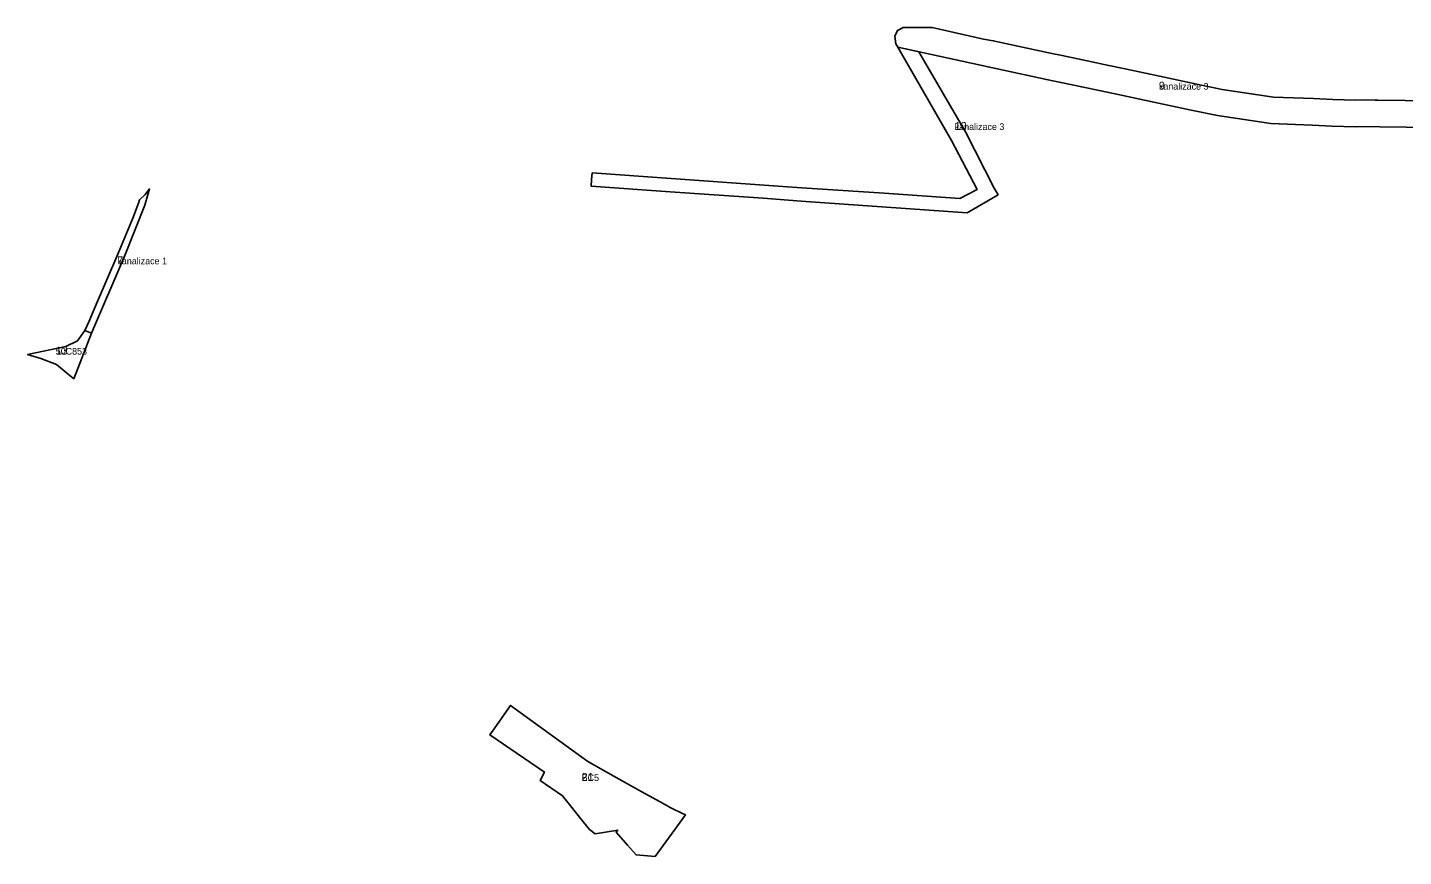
# Model space of a CAD drawing. Extents: x -540086 to -538022, y -1162553 to -1159940.
# Drawn here: x -540086 to -539054, y -1161871 to -1161249 of the extents above; entities that cross this region are included whole.
import ezdxf

# ---------------------------------------------------------------- set-up
doc = ezdxf.new("R2010")
doc.units = 0
for name, color, linetype in [('96120023', 7, 'Continuous'), ('96140023', 7, 'Continuous'), ('ID_VPO', 7, 'Continuous'), ('ID_VPS', 7, 'Continuous')]:
    doc.layers.add(name, color=color, linetype=linetype)

msp = doc.modelspace()

# ---------------------------------------------------------------- linework, layer by layer
at = {"layer": '96120023'}
msp.add_lwpolyline([(-539012.7, -1161324.2), (-539071.6, -1161323.6), (-539082.2, -1161323.2), (-539089.9, -1161323.5), (-539107.6, -1161323), (-539122.3, -1161322.3), (-539153.3, -1161321.1), (-539193.3, -1161315.1), (-539213, -1161311), (-539248, -1161303.6), (-539267.9, -1161299.3), (-539295.2, -1161293.6), (-539321.7, -1161288), (-539365.4, -1161278.6), (-539433.1, -1161263.8), (-539434.6, -1161261.2), (-539435.3, -1161255.5), (-539433.3, -1161251.1), (-539429.2, -1161249), (-539407.4, -1161249), (-539368.8, -1161257.7), (-539361.6, -1161258.9), (-539317.5, -1161268.5), (-539309.8, -1161270), (-539291.1, -1161274.1), (-539274.9, -1161277.6), (-539263.9, -1161279.7), (-539243.9, -1161284.1), (-539208.9, -1161291.4), (-539189.8, -1161295.4), (-539151.4, -1161301.2), (-539121.4, -1161302.3), (-539106.9, -1161303), (-539089.9, -1161303.5), (-539082.3, -1161303.2), (-539075.2, -1161303.5), (-539073, -1161303.6), (-539011.9, -1161304.2)], dxfattribs=at)
for points in [[(-539392.8, -1161333.7), (-539433.1, -1161263.8), (-539417.3, -1161267.2), (-539382.2, -1161327.9), (-539360.8, -1161369.6), (-539357.9, -1161374.6), (-539381.2, -1161388), (-539381.2, -1161388), (-539505.5, -1161379.2), (-539534.1, -1161377.1), (-539603.8, -1161372.2), (-539663.2, -1161368), (-539662.8, -1161363.3), (-539662.3, -1161358.1), (-539603.1, -1161362.2), (-539533.4, -1161367.2), (-539533.4, -1161367.2), (-539519.3, -1161368.3), (-539505.1, -1161369.2), (-539443.4, -1161373.2), (-539386.7, -1161377.3), (-539373.7, -1161370.6)], [(-540037.7, -1161478.4), (-540042.7, -1161476.5), (-540039.6, -1161469.5), (-540035.7, -1161460.3), (-540018.1, -1161419.2), (-540006.9, -1161392.1), (-540002.5, -1161380.9), (-540001.8, -1161378.3), (-539997.5, -1161374.2), (-539994.2, -1161370.1), (-539997.9, -1161382.2), (-540012.8, -1161420.2)], [(-540051, -1161512.6), (-540064, -1161501.8), (-540075.9, -1161497.3), (-540085.8, -1161494.4), (-540057.1, -1161488.4), (-540048.3, -1161484.2), (-540042.7, -1161476.5), (-540037.7, -1161478.4)]]:
    msp.add_lwpolyline(points, close=True, dxfattribs=at)
at = {"layer": '96140023'}
msp.add_lwpolyline([(-539603.3, -1161834.6), (-539594.1, -1161839.2), (-539592.4, -1161840), (-539615.1, -1161871.2), (-539629.4, -1161870), (-539635.9, -1161862.6), (-539644.3, -1161853), (-539643.1, -1161851.4), (-539660.1, -1161854.2), (-539664.3, -1161850.9), (-539668.8, -1161845.4), (-539684.6, -1161825.6), (-539701.4, -1161814.1), (-539698.2, -1161807.9), (-539739.2, -1161779.8), (-539735.4, -1161774.7), (-539723.6, -1161757.8), (-539665.7, -1161800), (-539644.3, -1161811.9), (-539622.9, -1161823.9), (-539611.4, -1161830.1)], close=True, dxfattribs=at)

# ---------------------------------------------------------------- texts
at = {"layer": '96120023'}
for s, rotation, p in [('kanalizace 3', 360, (-539237.3, -1161295.6)), ('kanalizace 3', 0, (-539390.4, -1161325.9)), ('kanalizace 1', 360, (-540018.4, -1161426.7)), ('50C853', 0, (-540064.6, -1161494.5))]:
    msp.add_text(s, height=5, rotation=rotation, dxfattribs=at).set_placement(p)
at = {"layer": '96140023'}
msp.add_text('BC5', height=5, rotation=0, dxfattribs=at).set_placement((-539670.2, -1161814.5))
at = {"layer": 'ID_VPO'}
msp.add_text('21', height=6, rotation=0, dxfattribs=at).set_placement((-539670.2, -1161814.5))
at = {"layer": 'ID_VPS'}
for s, rotation, p in [('9', 0, (-539237.3, -1161295.6)), ('10', 0, (-539390.4, -1161325.9)), ('7', 360, (-540018.4, -1161426.7)), ('13', 360, (-540064.6, -1161494.5))]:
    msp.add_text(s, height=6, rotation=rotation, dxfattribs=at).set_placement(p)

doc.saveas('drawing.dxf')
